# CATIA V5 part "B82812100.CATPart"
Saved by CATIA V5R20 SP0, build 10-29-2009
Part number: B82812100
Revision: 4
Definition: design
Nomenclature: B82812100
Source: made
Description: NOT SPECIFIED
Bounding box of the stored display mesh (mm): x -8 to 8, y -8 to 8, z 0 to 100
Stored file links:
  C:\Users\Raffaele\Desktop\3D X SITO CF\BOLEX\7-PILLAR REF 828\B82812100.CATPart
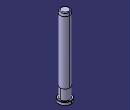
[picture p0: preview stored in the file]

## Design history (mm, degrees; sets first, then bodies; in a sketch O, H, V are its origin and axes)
Body1 "MANIFOLD_SOLID_BREP #450" (main body)
  Solid1: solid without history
